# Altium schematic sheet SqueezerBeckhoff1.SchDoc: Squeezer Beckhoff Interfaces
size B; Organization: LIGO Laboratory; Address1: California Institute of Technology; Address2: Massachusetts Institute of Technology; SheetNumber: 36; SheetTotal: 37; DrawnBy: R.  Abbott; Engineer: R.  Abbott; PageSetup: Record=PageOptions¦CenterHorizontal=True¦CenterVertical=True¦PrintScale=1.09¦XCorrection=1.00¦YCorrection=1.00¦PrintKind=0¦BorderSize=5000000¦LeftOffset=0¦BottomOffset=0¦Orientation=2¦PaperLength=1000¦PaperWidth=1000¦Scale=100¦PaperSource=7¦PrintQuality=-4¦MediaType=1¦DitherType=10¦PaperKind=11x17¦PrintScaleMode=1
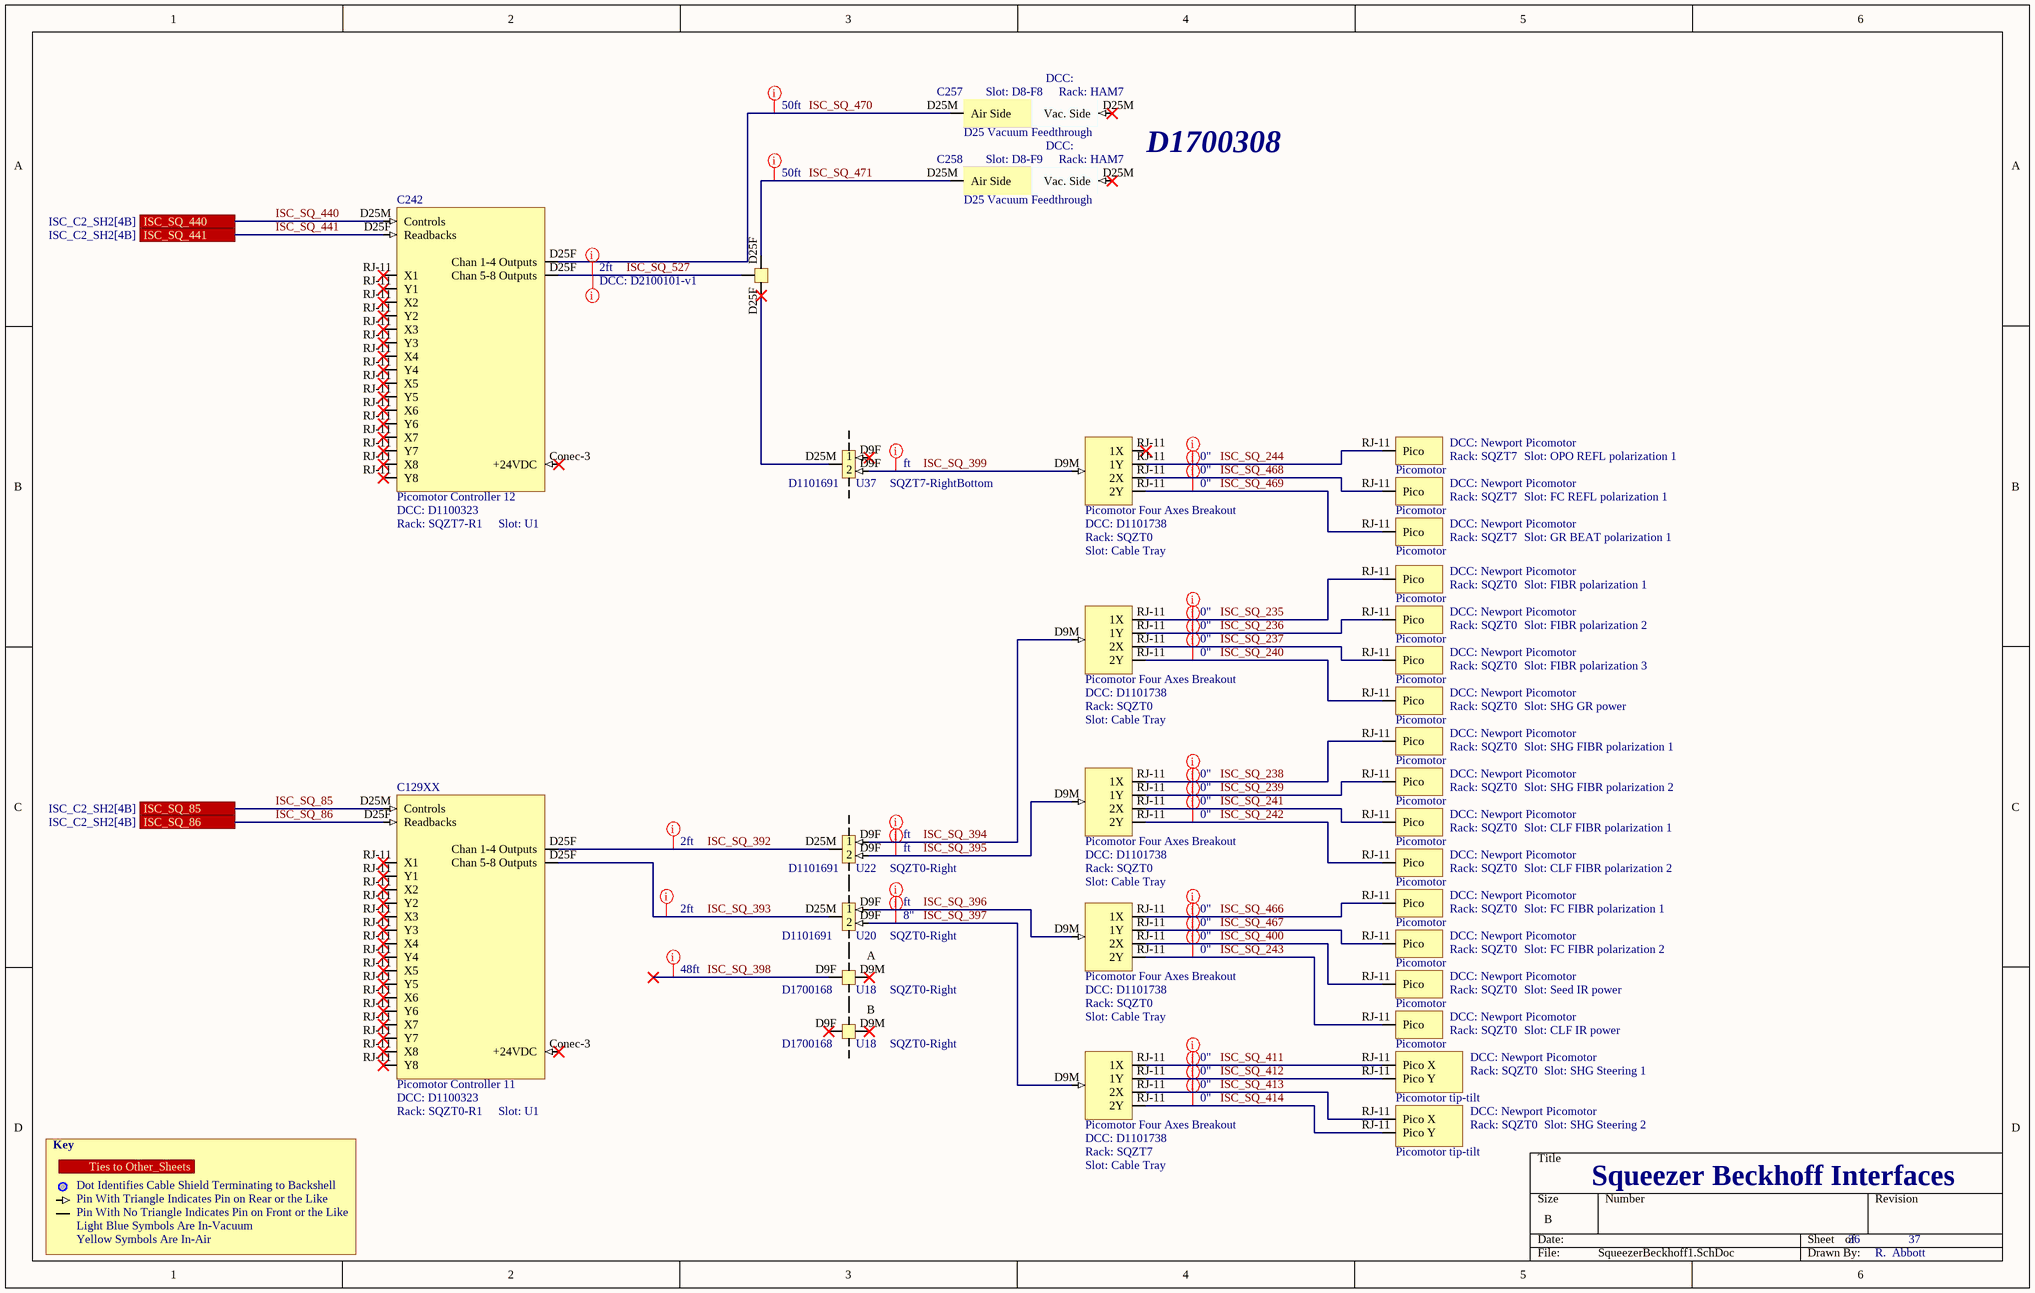
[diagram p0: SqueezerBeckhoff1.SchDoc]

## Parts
C129XX  Picomotor Controller 11  DCC: D1100323  Rack: SQZT0-R1  Slot: U1
C242  Picomotor Controller 12  DCC: D1100323  Rack: SQZT7-R1  Slot: U1
C243  Picomotor Four Axes Breakout  DCC: D1101738  Rack: SQZT0  Slot: Cable Tray
C244  Picomotor  DCC: Newport Picomotor  Rack: SQZT7  Slot: OPO REFL polarization 1
C245  Picomotor  DCC: Newport Picomotor  Rack: SQZT7  Slot: FC REFL polarization 1
C246  Picomotor  DCC: Newport Picomotor  Rack: SQZT0  Slot: FC FIBR polarization 1
C247  Picomotor  DCC: Newport Picomotor  Rack: SQZT0  Slot: FC FIBR polarization 2
C248  Picomotor  DCC: Newport Picomotor  Rack: SQZT0  Slot: CLF IR power
C257  D25 Vacuum Feedthrough  Rack: HAM7  Slot: D8-F8
C258  D25 Vacuum Feedthrough  Rack: HAM7  Slot: D8-F9
C282  Tee  (value not drawn)
C432  DCC: D1101691  Rack: SQZT0-Right  Slot: U22  (hidden comment: Patch Panel Picomotor Breakout)
C433  DCC: D1101691  Rack: SQZT0-Right  Slot: U20  (hidden comment: Patch Panel Picomotor Breakout)
C434  DCC: D1700168  Rack: SQZT0-Right  Slot: U18  (hidden comment: Patch Panel Picomotor DB9)  (parts A,B of 2)
C435  DCC: D1101691  Rack: SQZT7-RightBottom  Slot: U37  (hidden comment: Patch Panel Picomotor Breakout)
C436  Picomotor Four Axes Breakout  DCC: D1101738  Rack: SQZT0  Slot: Cable Tray
C437  Picomotor Four Axes Breakout  DCC: D1101738  Rack: SQZT0  Slot: Cable Tray
C438  Picomotor Four Axes Breakout  DCC: D1101738  Rack: SQZT0  Slot: Cable Tray
C439  Picomotor Four Axes Breakout  DCC: D1101738  Rack: SQZT7  Slot: Cable Tray
C440  Picomotor  DCC: Newport Picomotor  Rack: SQZT0  Slot: FIBR polarization 1
C441  Picomotor  DCC: Newport Picomotor  Rack: SQZT0  Slot: FIBR polarization 2
C442  Picomotor  DCC: Newport Picomotor  Rack: SQZT0  Slot: FIBR polarization 3
C443  Picomotor  DCC: Newport Picomotor  Rack: SQZT0  Slot: SHG FIBR polarization 1
C444  Picomotor  DCC: Newport Picomotor  Rack: SQZT0  Slot: SHG FIBR polarization 2
C445  Picomotor  DCC: Newport Picomotor  Rack: SQZT0  Slot: CLF FIBR polarization 1
C446  Picomotor  DCC: Newport Picomotor  Rack: SQZT0  Slot: CLF FIBR polarization 2
C447  Picomotor  DCC: Newport Picomotor  Rack: SQZT0  Slot: SHG GR power
C449  Picomotor  DCC: Newport Picomotor  Rack: SQZT0  Slot: Seed IR power
C450  Picomotor  DCC: Newport Picomotor  Rack: SQZT7  Slot: GR BEAT polarization 1
C451  Picomotor tip-tilt  DCC: Newport Picomotor  Rack: SQZT0  Slot: SHG Steering 1
C452  Picomotor tip-tilt  DCC: Newport Picomotor  Rack: SQZT0  Slot: SHG Steering 2

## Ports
ISC_SQ_85 (see ISC_C2_SH2[4B]), ISC_SQ_86 (see ISC_C2_SH2[4B]), ISC_SQ_440 (see ISC_C2_SH2[4B]), ISC_SQ_441 (see ISC_C2_SH2[4B]), Ties to Other_Sheets

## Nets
ISC_SQ_85: C129XX.D25M(Controls) ; port ISC_SQ_85
ISC_SQ_86: C129XX.D25F(Readbacks) ; port ISC_SQ_86
ISC_SQ_235: C436.RJ-11(1X) C440.RJ-11(Pico)
ISC_SQ_236: C436.RJ-11(1Y) C441.RJ-11(Pico)
ISC_SQ_237: C436.RJ-11(2X) C442.RJ-11(Pico)
ISC_SQ_238: C437.RJ-11(1X) C443.RJ-11(Pico)
ISC_SQ_239: C437.RJ-11(1Y) C444.RJ-11(Pico)
ISC_SQ_240: C436.RJ-11(2Y) C447.RJ-11(Pico)
ISC_SQ_241: C437.RJ-11(2X) C445.RJ-11(Pico)
ISC_SQ_242: C437.RJ-11(2Y) C446.RJ-11(Pico)
ISC_SQ_243: C248.RJ-11(Pico) C438.RJ-11(2Y)
ISC_SQ_244: C243.RJ-11(1X) C244.RJ-11(Pico)
ISC_SQ_392: C129XX.D25F(Chan_1-4_Outputs) C432.D25M(Pico)
ISC_SQ_393: C129XX.D25F(Chan_5-8_Outputs) C433.D25M(Pico)
ISC_SQ_394: C432.D9F C436.D9M(IN)
ISC_SQ_395: C432.D9F C437.D9M(IN)
ISC_SQ_396: C433.D9F C438.D9M(IN)
ISC_SQ_397: C433.D9F C439.D9M(IN)
ISC_SQ_398: C434.D9F(A)
ISC_SQ_399: C243.D9M(IN) C435.D9F
ISC_SQ_400: C438.RJ-11(2X) C449.RJ-11(Pico)
ISC_SQ_411: C439.RJ-11(1X) C451.RJ-11(Pico_X)
ISC_SQ_412: C439.RJ-11(1Y) C451.RJ-11(Pico_Y)
ISC_SQ_413: C439.RJ-11(2X) C452.RJ-11(Pico_X)
ISC_SQ_414: C439.RJ-11(2Y) C452.RJ-11(Pico_Y)
ISC_SQ_440: C242.D25M(Controls) ; port ISC_SQ_440
ISC_SQ_441: C242.D25F(Readbacks) ; port ISC_SQ_441
ISC_SQ_466: C246.RJ-11(Pico) C438.RJ-11(1X)
ISC_SQ_467: C247.RJ-11(Pico) C438.RJ-11(1Y)
ISC_SQ_468: C243.RJ-11(2X) C245.RJ-11(Pico)
ISC_SQ_469: C243.RJ-11(2Y) C450.RJ-11(Pico)
ISC_SQ_470: C242.D25F(Chan_1-4_Outputs) C257.D25M(Vac._Side)
ISC_SQ_471: C258.D25M(Vac._Side) C282.D25F
ISC_SQ_527: C242.D25F(Chan_5-8_Outputs) C282.D25MM
NetC282_D25F: C282.D25F C435.D25M(Pico)

Not connected (* = marked no-connect by the designer): C129XX Conec-3(+24VDC)* RJ-11(X1)*; C242 Conec-3(+24VDC)* RJ-11(X1)*; C434 D9M(A)*

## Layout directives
Length: 2ft: ISC_SQ_392, ISC_SQ_393, ISC_SQ_527
Length: 48ft: ISC_SQ_398
Length: 8": ISC_SQ_397
Length: ft: ISC_SQ_394, ISC_SQ_395, ISC_SQ_396, ISC_SQ_399
Length: 0": ISC_SQ_235, ISC_SQ_236, ISC_SQ_237, ISC_SQ_238, ISC_SQ_239, ISC_SQ_240, ISC_SQ_241, ISC_SQ_242, ISC_SQ_243, ISC_SQ_244, ISC_SQ_400, ISC_SQ_411, ISC_SQ_412, ISC_SQ_413, ISC_SQ_414, ISC_SQ_466, ISC_SQ_467, ISC_SQ_468, ISC_SQ_469
DCC: D2100101-v1: ISC_SQ_527
Length: 50ft: ISC_SQ_470, ISC_SQ_471

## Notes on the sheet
- D1700308
- Key
- Dot Identifies Cable Shield Terminating to Backshell
- Pin With Triangle Indicates Pin on Rear or the Like
- Pin With No Triangle Indicates Pin on Front or the Like
- Light Blue Symbols Are In-Vacuum
- Yellow Symbols Are In-Air

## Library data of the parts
C129XX C242 = Picomotor Driver: Serial: Sxxxxxxx; System: ISC
C243 C436-C439 = Picomotor Four Axes Breakout: Serial: Sxxxxxxx; System: ISC
C244-C248 C440-C447 C449 C450 = Picomotor: Serial: Sxxxxxxx; System: ISC
C257 C258 = VacFeedD25: Serial: Sxxxxxxx; System: ISC
C282 = TNC Tee: Tee (TNC); Serial: Sxxxxxxx; System: ISC; DCC: D2100101; Rack: SQZT7-R1; Slot: U1
C432 C433 C435 = Patch Panel Picomotor Breakout: Patch Panel (D1101691); Serial: Sxxxxxxx; System: ISC
C434 = Patch Panel Picomotor DB9: Patch Panel (D1700168); Serial: Sxxxxxxx; System: ISC
C451 C452 = Picomotor 2-axes: Serial: Sxxxxxxx; System: ISC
